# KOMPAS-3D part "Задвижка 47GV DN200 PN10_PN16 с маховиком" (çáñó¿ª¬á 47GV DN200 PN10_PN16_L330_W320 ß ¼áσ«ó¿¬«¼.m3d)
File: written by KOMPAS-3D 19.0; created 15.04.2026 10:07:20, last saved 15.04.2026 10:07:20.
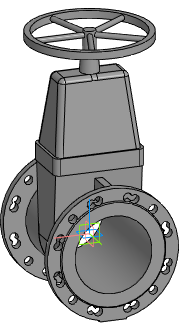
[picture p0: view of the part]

Document properties: Автор: Евгений; Полное имя файла: Z:\3.Личные\kachalov\3d для проектировщиков\2.1 Тип 47GV, 47GV.Z\Задвижка 47GV_DN40-DN600\stp_Задвижка 47GV\Задвижка 47GV DN200 PN10_PN16_L330_W320 с маховиком.m3d

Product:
- Part/product: Задвижка 47GV DN200 PN10_PN16 с маховиком

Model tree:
1. Операция без истории:1  (labels: Задвижка 47GV DN200 PN10_PN16 с маховиком)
